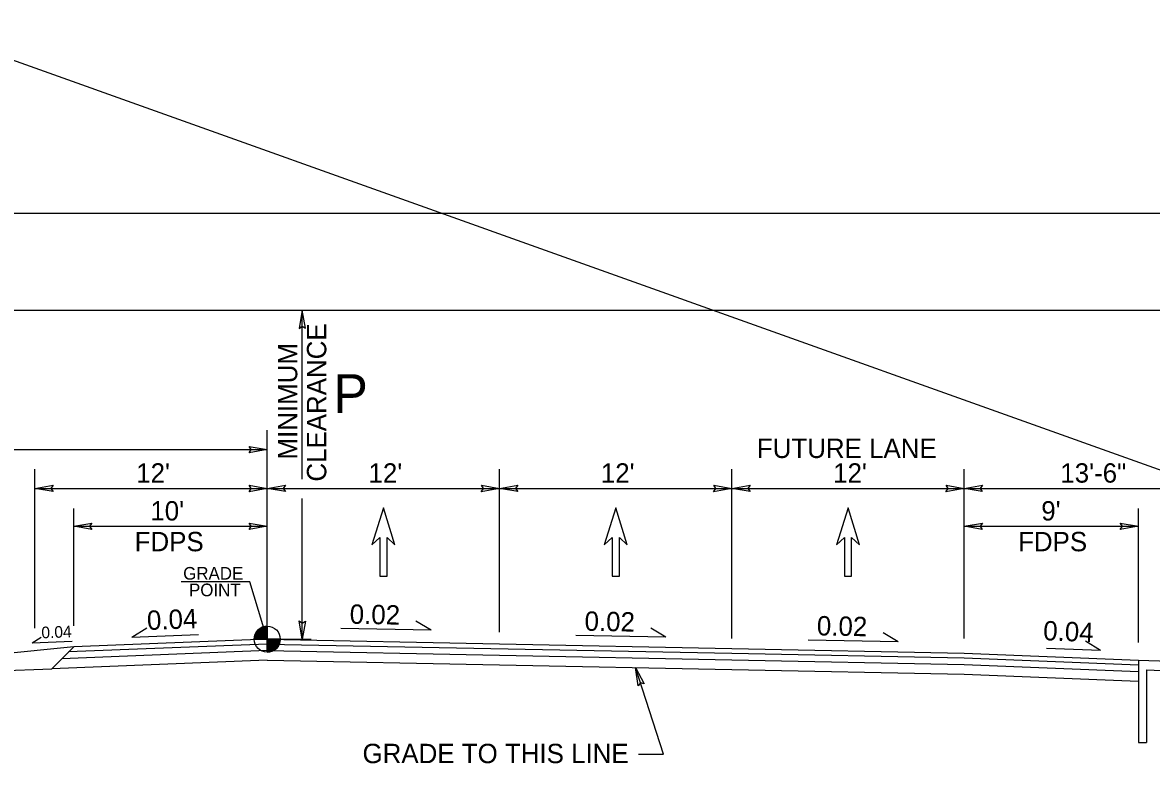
# Model space of a CAD drawing. Extents: x 1553195 to 1553792, y 810516 to 810787.
# Drawn here: x 1553561.6 to 1553619.9, y 810530.1 to 810568.3 of the extents above; entities that cross this region are included whole.
import ezdxf

# ---------------------------------------------------------------- set-up
doc = ezdxf.new("R2010")
doc.units = 0
for name, color, linetype in [('Old_Level_11', 7, 'Continuous'), ('Prop Dimension', 7, 'Continuous'), ('Prop DSN Text', 7, 'Continuous'), ('Prop Pavement Schedule Description CELL', 7, 'Continuous'), ('Prop Typical Section', 7, 'Continuous'), ('Sheet Sticker Incomplete CELL', 7, 'Continuous'), ('Typical Arrow Superelevation CELL', 7, 'Continuous'), ('Typical Pavement Slope CELL', 7, 'Continuous'), ('Typical Text ID Circle CELL', 7, 'Continuous'), ('z - Construction', 7, 'Continuous')]:
    doc.layers.add(name, color=color, linetype=linetype)

msp = doc.modelspace()

# ---------------------------------------------------------------- linework, layer by layer
at = {"layer": 'Old_Level_11'}
for p, q in [((1553574.205, 810536.478), (1553574.205, 810537.149)), ((1553573.534, 810536.478), (1553574.205, 810536.478)), ((1553574.206, 810535.806), (1553574.205, 810536.478)), ((1553574.876, 810536.478), (1553574.205, 810536.478)), ((1553574.205, 810536.478), (1553574.206, 810535.806))]:
    msp.add_line(p, q, dxfattribs=at)
for points in [[(1553573.554, 810536.642), (1553573.554, 810536.478)], [(1553573.568, 810536.688), (1553573.568, 810536.478)], [(1553573.581, 810536.725), (1553573.581, 810536.478)], [(1553573.595, 810536.757), (1553573.595, 810536.478)], [(1553573.608, 810536.785), (1553573.608, 810536.478)], [(1553573.622, 810536.809), (1553573.622, 810536.478)], [(1553573.635, 810536.831), (1553573.635, 810536.478)], [(1553573.648, 810536.852), (1553573.648, 810536.478)], [(1553573.662, 810536.872), (1553573.662, 810536.478)], [(1553573.675, 810536.89), (1553573.675, 810536.478)], [(1553573.689, 810536.906), (1553573.689, 810536.478)], [(1553573.702, 810536.922), (1553573.702, 810536.478)], [(1553573.716, 810536.937), (1553573.716, 810536.478)], [(1553573.729, 810536.951), (1553573.729, 810536.478)], [(1553573.742, 810536.964), (1553573.742, 810536.478)], [(1553573.756, 810536.976), (1553573.756, 810536.478)], [(1553573.769, 810536.988), (1553573.769, 810536.478)], [(1553573.783, 810537), (1553573.783, 810536.478)], [(1553573.796, 810537.01), (1553573.796, 810536.478)], [(1553573.809, 810537.019), (1553573.809, 810536.478)], [(1553573.823, 810537.03), (1553573.823, 810536.478)], [(1553573.836, 810537.039), (1553573.836, 810536.478)], [(1553573.85, 810537.048), (1553573.85, 810536.478)], [(1553573.863, 810537.055), (1553573.863, 810536.478)], [(1553573.877, 810537.063), (1553573.877, 810536.478)], [(1553573.89, 810537.07), (1553573.89, 810536.478)], [(1553573.903, 810537.078), (1553573.903, 810536.478)], [(1553573.917, 810537.084), (1553573.917, 810536.478)], [(1553573.93, 810537.089), (1553573.93, 810536.478)], [(1553573.944, 810537.096), (1553573.944, 810536.478)], [(1553573.957, 810537.101), (1553573.957, 810536.478)], [(1553573.971, 810537.107), (1553573.971, 810536.478)], [(1553573.984, 810537.112), (1553573.984, 810536.478)], [(1553573.998, 810537.116), (1553573.998, 810536.478)], [(1553574.011, 810537.121), (1553574.011, 810536.478)], [(1553574.024, 810537.124), (1553574.024, 810536.478)], [(1553574.038, 810537.128), (1553574.038, 810536.478)], [(1553574.051, 810537.131), (1553574.051, 810536.478)], [(1553574.065, 810537.134), (1553574.065, 810536.478)], [(1553574.078, 810537.137), (1553574.078, 810536.478)], [(1553574.091, 810537.14), (1553574.091, 810536.478)], [(1553574.105, 810537.142), (1553574.105, 810536.478)], [(1553574.118, 810537.143), (1553574.118, 810536.478)], [(1553574.132, 810537.145), (1553574.132, 810536.478)], [(1553574.145, 810537.146), (1553574.145, 810536.478)], [(1553574.159, 810537.148), (1553574.159, 810536.478)], [(1553574.172, 810537.148), (1553574.172, 810536.478)], [(1553574.185, 810537.149), (1553574.185, 810536.478)], [(1553574.199, 810537.149), (1553574.199, 810537.149), (1553574.199, 810536.478)], [(1553573.541, 810536.573), (1553573.541, 810536.478)], [(1553574.215, 810536.478), (1553574.215, 810535.806), (1553574.215, 810535.806)], [(1553574.229, 810536.478), (1553574.229, 810535.806)], [(1553574.242, 810536.478), (1553574.242, 810535.808)], [(1553574.256, 810536.478), (1553574.256, 810535.808)], [(1553574.269, 810536.478), (1553574.269, 810535.809)], [(1553574.282, 810536.478), (1553574.282, 810535.811)], [(1553574.296, 810536.478), (1553574.296, 810535.812)], [(1553574.309, 810536.478), (1553574.309, 810535.815)], [(1553574.323, 810536.478), (1553574.323, 810535.817)], [(1553574.336, 810536.478), (1553574.336, 810535.82)], [(1553574.35, 810536.478), (1553574.35, 810535.823)], [(1553574.363, 810536.478), (1553574.363, 810535.826)], [(1553574.376, 810536.478), (1553574.376, 810535.829)], [(1553574.39, 810536.478), (1553574.39, 810535.833)], [(1553574.403, 810536.478), (1553574.403, 810535.836)], [(1553574.417, 810536.478), (1553574.417, 810535.841)], [(1553574.43, 810536.478), (1553574.43, 810535.845)], [(1553574.444, 810536.478), (1553574.444, 810535.85)], [(1553574.457, 810536.478), (1553574.457, 810535.856)], [(1553574.47, 810536.478), (1553574.47, 810535.862)], [(1553574.484, 810536.478), (1553574.484, 810535.868)], [(1553574.497, 810536.478), (1553574.497, 810535.874)], [(1553574.511, 810536.478), (1553574.511, 810535.88)], [(1553574.524, 810536.478), (1553574.524, 810535.887)], [(1553574.538, 810536.478), (1553574.538, 810535.894)], [(1553574.551, 810536.478), (1553574.551, 810535.902)], [(1553574.564, 810536.478), (1553574.564, 810535.911)], [(1553574.578, 810536.478), (1553574.578, 810535.92)], [(1553574.591, 810536.478), (1553574.591, 810535.929)], [(1553574.605, 810536.478), (1553574.605, 810535.938)], [(1553574.618, 810536.478), (1553574.618, 810535.948)], [(1553574.632, 810536.478), (1553574.632, 810535.959)], [(1553574.645, 810536.478), (1553574.645, 810535.971)], [(1553574.658, 810536.478), (1553574.658, 810535.982)], [(1553574.672, 810536.478), (1553574.672, 810535.994)], [(1553574.685, 810536.478), (1553574.685, 810536.008)], [(1553574.699, 810536.478), (1553574.699, 810536.023)], [(1553574.712, 810536.478), (1553574.712, 810536.038)], [(1553574.726, 810536.478), (1553574.726, 810536.054)], [(1553574.739, 810536.478), (1553574.739, 810536.071)], [(1553574.752, 810536.478), (1553574.752, 810536.088)], [(1553574.766, 810536.478), (1553574.766, 810536.108)], [(1553574.779, 810536.478), (1553574.779, 810536.129)], [(1553574.793, 810536.478), (1553574.793, 810536.153)], [(1553574.806, 810536.478), (1553574.806, 810536.178)], [(1553574.82, 810536.478), (1553574.82, 810536.206)], [(1553574.833, 810536.478), (1553574.833, 810536.238)], [(1553574.846, 810536.478), (1553574.846, 810536.278)], [(1553574.86, 810536.478), (1553574.86, 810536.326)], [(1553574.873, 810536.478), (1553574.873, 810536.405)]]:
    msp.add_lwpolyline(points, dxfattribs=at)
msp.add_circle((1553574.206, 810536.478), 0.671, dxfattribs=at)
for start, end in [(90.00952, 180.00952), (270.00952, 0.00952)]:
    msp.add_arc((1553574.206, 810536.478), 0.671, start, end, dxfattribs=at)
at = {"layer": 'Prop Dimension'}
for p, q in [((1553582.672, 810536.942), (1553581.889, 810537.415)), ((1553562.066, 810536.293), (1553562.53, 810536.586)), ((1553567.205, 810536.574), (1553567.979, 810537.063)), ((1553567.205, 810536.574), (1553570.655, 810536.712)), ((1553582.672, 810536.942), (1553578.012, 810537.035)), ((1553594.803, 810536.58), (1553590.143, 810536.674)), ((1553594.803, 810536.58), (1553594.02, 810537.054)), ((1553606.803, 810536.34), (1553606.02, 810536.814)), ((1553562.066, 810536.293), (1553564.136, 810536.375)), ((1553606.803, 810536.34), (1553602.143, 810536.434)), ((1553617.248, 810535.891), (1553614.453, 810536.003)), ((1553617.248, 810535.891), (1553616.475, 810536.38))]:
    msp.add_line(p, q, dxfattribs=at)
at = {"layer": 'Prop DSN Text'}
for points in [[(1553576.177, 810552.541), (1553576.015, 810553.478), (1553575.849, 810552.535), (1553576.015, 810552.655)], [(1553573.268, 810546.438), (1553574.206, 810546.277), (1553573.263, 810546.11), (1553573.383, 810546.277)], [(1553563.143, 810544.103), (1553562.206, 810544.264), (1553563.148, 810544.431), (1553563.028, 810544.264)], [(1553573.268, 810544.426), (1553574.206, 810544.264), (1553573.263, 810544.098), (1553573.383, 810544.264)], [(1553575.143, 810544.103), (1553574.206, 810544.264), (1553575.148, 810544.431), (1553575.028, 810544.264)], [(1553585.268, 810544.426), (1553586.206, 810544.264), (1553585.263, 810544.098), (1553585.383, 810544.264)], [(1553587.143, 810544.103), (1553586.206, 810544.264), (1553587.148, 810544.431), (1553587.028, 810544.264)], [(1553597.268, 810544.426), (1553598.206, 810544.264), (1553597.263, 810544.098), (1553597.383, 810544.264)], [(1553599.143, 810544.103), (1553598.206, 810544.264), (1553599.148, 810544.431), (1553599.028, 810544.264)], [(1553609.268, 810544.426), (1553610.206, 810544.264), (1553609.263, 810544.098), (1553609.383, 810544.264)], [(1553611.143, 810544.103), (1553610.206, 810544.264), (1553611.148, 810544.431), (1553611.028, 810544.264)], [(1553565.143, 810542.147), (1553564.206, 810542.309), (1553565.148, 810542.476), (1553565.028, 810542.309)], [(1553573.268, 810542.47), (1553574.206, 810542.309), (1553573.263, 810542.142), (1553573.383, 810542.309)], [(1553611.143, 810542.147), (1553610.206, 810542.309), (1553611.148, 810542.476), (1553611.028, 810542.309)], [(1553618.268, 810542.47), (1553619.206, 810542.309), (1553618.263, 810542.142), (1553618.383, 810542.309)], [(1553576.177, 810537.415), (1553576.015, 810536.478), (1553575.849, 810537.421), (1553576.015, 810537.301)], [(1553593.365, 810534.072), (1553593.232, 810535.014), (1553593.679, 810534.168), (1553593.484, 810534.231)]]:
    msp.add_lwpolyline(points, close=True, dxfattribs=at)
at = {"layer": 'Prop Pavement Schedule Description CELL'}
for p, q in [((1553594.673, 810530.531), (1553593.232, 810535.014)), ((1553593.39, 810530.531), (1553594.673, 810530.531))]:
    msp.add_line(p, q, dxfattribs=at)
at = {"layer": 'Prop Typical Section'}
for points in [[(1553579.612, 810541.358), (1553580.018, 810541.733), (1553580.018, 810539.733), (1553580.393, 810539.733), (1553580.393, 810541.733), (1553580.799, 810541.358), (1553580.206, 810543.264)], [(1553591.612, 810541.358), (1553592.018, 810541.733), (1553592.018, 810539.733), (1553592.393, 810539.733), (1553592.393, 810541.733), (1553592.799, 810541.358), (1553592.206, 810543.264)], [(1553603.612, 810541.358), (1553604.018, 810541.733), (1553604.018, 810539.733), (1553604.393, 810539.733), (1553604.393, 810541.733), (1553604.799, 810541.358), (1553604.206, 810543.264)]]:
    msp.add_lwpolyline(points, close=True, dxfattribs=at)
at = {"layer": 'Sheet Sticker Incomplete CELL'}
for p, q in [((1553564.206, 810536.078), (1553544.206, 810534.078)), ((1553546.15, 810534.272), (1553563.077, 810534.95))]:
    msp.add_line(p, q, dxfattribs=at)
at = {"layer": 'Typical Arrow Superelevation CELL'}
for p, q in [((1553448.543, 810606.601), (1553652.472, 810533.73)), ((1553446.448, 810558.478), (1553641.963, 810558.478)), ((1553446.448, 810553.478), (1553641.963, 810553.478)), ((1553619.206, 810535.398), (1553619.206, 810531.142)), ((1553619.206, 810535.398), (1553620.832, 810535.334)), ((1553619.628, 810534.893), (1553619.628, 810531.142)), ((1553619.628, 810534.893), (1553620.813, 810534.846)), ((1553619.206, 810531.142), (1553619.628, 810531.142))]:
    msp.add_line(p, q, dxfattribs=at)
at = {"layer": 'Typical Pavement Slope CELL'}
for p, q in [((1553564.206, 810536.078), (1553563.077, 810534.95)), ((1553574.206, 810536.228), (1553563.945, 810535.818)), ((1553574.206, 810536.478), (1553564.206, 810536.078)), ((1553574.206, 810536.478), (1553598.206, 810535.998)), ((1553574.206, 810536.228), (1553598.206, 810535.748)), ((1553598.206, 810535.998), (1553610.206, 810535.758)), ((1553574.206, 810535.895), (1553563.598, 810535.47)), ((1553574.206, 810535.895), (1553598.206, 810535.415)), ((1553598.206, 810535.748), (1553610.206, 810535.508)), ((1553598.206, 810535.415), (1553610.206, 810535.175)), ((1553610.206, 810535.758), (1553619.206, 810535.398)), ((1553610.206, 810535.508), (1553619.206, 810535.148)), ((1553574.206, 810535.395), (1553563.077, 810534.95)), ((1553574.206, 810535.395), (1553598.206, 810534.915)), ((1553598.206, 810534.915), (1553610.206, 810534.675)), ((1553610.206, 810535.175), (1553619.206, 810534.815)), ((1553610.206, 810534.675), (1553619.206, 810534.315))]:
    msp.add_line(p, q, dxfattribs=at)
at = {"layer": 'Typical Text ID Circle CELL'}
msp.add_lwpolyline([(1553574.206, 810536.478), (1553573.302, 810539.432), (1553569.764, 810539.432)], dxfattribs=at)
at = {"layer": 'z - Construction'}
for p, q in [((1553576.015, 810544.746), (1553576.015, 810553.478)), ((1553574.206, 810537.167), (1553574.206, 810547.267)), ((1553544.206, 810546.277), (1553574.206, 810546.277)), ((1553562.206, 810537.049), (1553562.206, 810545.264)), ((1553586.206, 810536.841), (1553586.206, 810545.264)), ((1553598.206, 810536.518), (1553598.206, 810545.264)), ((1553610.206, 810536.518), (1553610.206, 810545.264)), ((1553562.206, 810544.264), (1553574.206, 810544.264)), ((1553574.206, 810544.264), (1553586.206, 810544.264)), ((1553586.206, 810544.264), (1553598.206, 810544.264)), ((1553598.206, 810544.264), (1553610.206, 810544.264)), ((1553610.206, 810544.264), (1553623.706, 810544.264)), ((1553576.015, 810536.478), (1553576.015, 810543.752)), ((1553564.206, 810537.167), (1553564.206, 810543.223)), ((1553619.206, 810536.314), (1553619.206, 810543.223)), ((1553564.206, 810542.309), (1553574.206, 810542.309)), ((1553610.206, 810542.309), (1553619.206, 810542.309)), ((1553574.206, 810536.478), (1553576.469, 810536.478))]:
    msp.add_line(p, q, dxfattribs=at)

# ---------------------------------------------------------------- texts
at = {"layer": 'Prop Pavement Schedule Description CELL'}
for s, height, rotation, p in [('CLEARANCE', 1, 90, (1553577.256, 810544.618)), ('MINIMUM', 1, 90, (1553575.756, 810545.761)), ('0.04', 1, 2.29061, (1553568.012, 810536.949)), ('0.02', 1, 358.85413, (1553578.457, 810537.279)), ('0.02', 1, 358.85413, (1553590.588, 810536.918)), ('0.04', 0.6, 2.29061, (1553562.551, 810536.518)), ('0.02', 1, 358.85413, (1553602.588, 810536.678)), ('0.04', 1, 357.70939, (1553614.273, 810536.428))]:
    msp.add_text(s, height=height, rotation=rotation, dxfattribs=at).set_placement(p)
for s, height, p in [('P', 2, (1553577.621, 810548.165)), ('FUTURE LANE', 1, (1553599.499, 810545.837)), ("12'", 1, (1553567.437, 810544.565)), ("12'", 1, (1553579.437, 810544.565)), ("12'", 1, (1553591.437, 810544.565)), ("12'", 1, (1553603.437, 810544.565)), ('13\'-6"', 1, (1553615.172, 810544.565)), ("10'", 1, (1553568.167, 810542.609)), ("9'", 1, (1553614.188, 810542.609)), ('FDPS', 1, (1553567.357, 810541.019)), ('FDPS', 1, (1553612.99, 810541.019)), ('GRADE TO THIS LINE', 1, (1553579.127, 810530.074))]:
    msp.add_text(s, height=height, dxfattribs=at).set_placement(p)
at = {"layer": 'Typical Text ID Circle CELL'}
for s, p in [('GRADE', (1553569.863, 810539.554)), ('POINT', (1553570.164, 810538.696))]:
    msp.add_text(s, height=0.6525, dxfattribs=at).set_placement(p)

doc.saveas('drawing.dxf')
